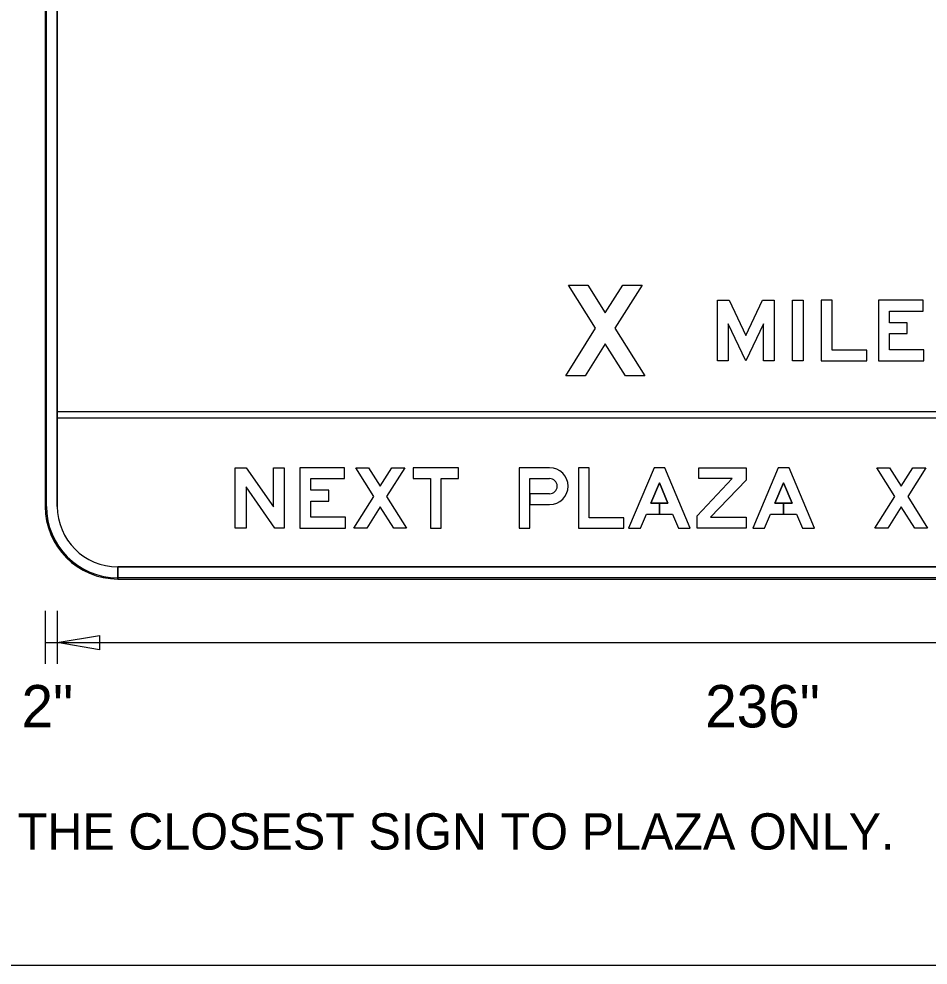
# Model space of a CAD drawing. Extents: x 17890484 to 17890754, y 17897495 to 17897992.
# Drawn here: x 17890528.32 to 17890540.84, y 17897572.57 to 17897585.59 of the extents above; entities that cross this region are included whole.
import ezdxf

# ---------------------------------------------------------------- set-up
doc = ezdxf.new("R2010")
doc.units = 0
for name, color, linetype in [('GSBWFill', 7, 'Continuous'), ('GSColorFill', 7, 'Continuous'), ('GSDims', 7, 'Continuous'), ('GSOutline', 7, 'Continuous'), ('SheetLinesMisc2_dp', 7, 'Continuous')]:
    doc.layers.add(name, color=color, linetype=linetype)

msp = doc.modelspace()

# ---------------------------------------------------------------- linework, layer by layer
at = {"layer": 'GSBWFill'}
for p, q in [((17890528.683, 17897590.883), (17890528.683, 17897578.883)), ((17890528.85, 17897578.883), (17890528.85, 17897590.883)), ((17890548.517, 17897580.186), (17890528.85, 17897580.186)), ((17890528.85, 17897580.186), (17890528.85, 17897580.103)), ((17890528.85, 17897580.103), (17890548.517, 17897580.103)), ((17890535.359, 17897579.265), (17890535.63, 17897579.265)), ((17890529.683, 17897577.883), (17890529.683, 17897578.049)), ((17890547.683, 17897578.049), (17890529.685, 17897578.049)), ((17890529.685, 17897578.049), (17890529.685, 17897577.883)), ((17890529.685, 17897577.883), (17890547.683, 17897577.883))]:
    msp.add_line(p, q, dxfattribs=at)
for points in [[(17890536.674, 17897580.678), (17890536.396, 17897581.121), (17890536.118, 17897580.678), (17890535.852, 17897580.678), (17890536.263, 17897581.333), (17890535.89, 17897581.928), (17890536.155, 17897581.928), (17890536.396, 17897581.544), (17890536.636, 17897581.928), (17890536.902, 17897581.928), (17890536.529, 17897581.333), (17890536.94, 17897580.678)], [(17890538.331, 17897581.235), (17890538.561, 17897581.719), (17890538.723, 17897581.719), (17890538.723, 17897580.886), (17890538.573, 17897580.886), (17890538.573, 17897581.394), (17890538.331, 17897580.886), (17890538.09, 17897581.394), (17890538.09, 17897580.886), (17890537.94, 17897580.886), (17890537.94, 17897581.719), (17890538.101, 17897581.719)], [(17890538.972, 17897580.886), (17890538.972, 17897581.719), (17890539.122, 17897581.719), (17890539.122, 17897580.886)], [(17890539.996, 17897580.886), (17890539.996, 17897581.032), (17890539.521, 17897581.032), (17890539.521, 17897581.719), (17890539.371, 17897581.719), (17890539.371, 17897580.886)], [(17890540.784, 17897581.036), (17890540.309, 17897581.036), (17890540.309, 17897581.26), (17890540.555, 17897581.26), (17890540.555, 17897581.41), (17890540.309, 17897581.41), (17890540.309, 17897581.569), (17890540.772, 17897581.569), (17890540.772, 17897581.719), (17890540.159, 17897581.719), (17890540.159, 17897580.886), (17890540.784, 17897580.886)], [(17890531.976, 17897579.415), (17890531.976, 17897578.582), (17890531.846, 17897578.582), (17890531.451, 17897579.152), (17890531.451, 17897578.582), (17890531.301, 17897578.582), (17890531.301, 17897579.415), (17890531.451, 17897579.415), (17890531.826, 17897578.875), (17890531.826, 17897579.415)], [(17890532.817, 17897578.732), (17890532.342, 17897578.732), (17890532.342, 17897578.956), (17890532.588, 17897578.956), (17890532.588, 17897579.106), (17890532.342, 17897579.106), (17890532.342, 17897579.265), (17890532.805, 17897579.265), (17890532.805, 17897579.415), (17890532.192, 17897579.415), (17890532.192, 17897578.582), (17890532.817, 17897578.582)], [(17890533.482, 17897578.582), (17890533.296, 17897578.877), (17890533.111, 17897578.582), (17890532.934, 17897578.582), (17890533.208, 17897579.018), (17890532.959, 17897579.415), (17890533.136, 17897579.415), (17890533.296, 17897579.159), (17890533.457, 17897579.415), (17890533.634, 17897579.415), (17890533.385, 17897579.018), (17890533.659, 17897578.582)], [(17890533.751, 17897579.265), (17890533.988, 17897579.265), (17890533.988, 17897578.582), (17890534.138, 17897578.582), (17890534.138, 17897579.265), (17890534.376, 17897579.265), (17890534.376, 17897579.415), (17890533.751, 17897579.415)], [(17890536.651, 17897578.582), (17890536.651, 17897578.727), (17890536.176, 17897578.727), (17890536.176, 17897579.415), (17890536.026, 17897579.415), (17890536.026, 17897578.582)], [(17890537.259, 17897578.927), (17890537.142, 17897578.927), (17890537.142, 17897578.777), (17890537.322, 17897578.777), (17890537.404, 17897578.582), (17890537.567, 17897578.582), (17890537.217, 17897579.415), (17890537.067, 17897579.415), (17890536.717, 17897578.582), (17890536.88, 17897578.582), (17890536.962, 17897578.777), (17890537.142, 17897578.777), (17890537.142, 17897578.927), (17890537.025, 17897578.927), (17890537.142, 17897579.206)], [(17890538.334, 17897578.732), (17890538.334, 17897578.582), (17890537.659, 17897578.582), (17890537.659, 17897578.752), (17890538.143, 17897579.265), (17890537.684, 17897579.265), (17890537.684, 17897579.415), (17890538.334, 17897579.415), (17890538.334, 17897579.244), (17890537.846, 17897578.732)], [(17890538.968, 17897578.927), (17890538.851, 17897578.927), (17890538.851, 17897578.777), (17890539.031, 17897578.777), (17890539.113, 17897578.582), (17890539.276, 17897578.582), (17890538.926, 17897579.415), (17890538.776, 17897579.415), (17890538.426, 17897578.582), (17890538.588, 17897578.582), (17890538.67, 17897578.777), (17890538.851, 17897578.777), (17890538.851, 17897578.927), (17890538.733, 17897578.927), (17890538.851, 17897579.206)], [(17890540.657, 17897578.582), (17890540.471, 17897578.877), (17890540.286, 17897578.582), (17890540.109, 17897578.582), (17890540.383, 17897579.018), (17890540.134, 17897579.415), (17890540.311, 17897579.415), (17890540.471, 17897579.159), (17890540.632, 17897579.415), (17890540.809, 17897579.415), (17890540.56, 17897579.018), (17890540.834, 17897578.582)]]:
    msp.add_lwpolyline(points, close=True, dxfattribs=at)
for points in [[(17890535.63, 17897579.415), (17890535.209, 17897579.415), (17890535.209, 17897578.582), (17890535.359, 17897578.582), (17890535.359, 17897579.265)], [(17890535.63, 17897579.057), (17890535.359, 17897579.057), (17890535.359, 17897578.907), (17890535.63, 17897578.907)]]:
    msp.add_lwpolyline(points, dxfattribs=at)
for radius in [1, 0.833]:
    msp.add_arc((17890529.683, 17897578.883), radius, 180, 270, dxfattribs=at)
for major_axis in [(0, 0.254), (0, 0.104)]:
    msp.add_ellipse((17890535.63, 17897579.161), major_axis=major_axis, ratio=0.999994, start_param=3.141593, end_param=6.283185, dxfattribs=at)
at = {"layer": 'GSColorFill'}
for p, q in [((17890528.683, 17897590.883), (17890528.683, 17897578.883)), ((17890528.683, 17897590.883), (17890528.683, 17897578.883)), ((17890528.683, 17897590.883), (17890528.683, 17897578.883)), ((17890528.7, 17897578.883), (17890528.7, 17897590.883)), ((17890528.85, 17897578.883), (17890528.85, 17897590.883)), ((17890548.517, 17897580.186), (17890528.85, 17897580.186)), ((17890528.85, 17897580.186), (17890528.85, 17897580.103)), ((17890528.85, 17897580.103), (17890548.517, 17897580.103)), ((17890535.359, 17897579.265), (17890535.63, 17897579.265)), ((17890529.683, 17897577.883), (17890529.683, 17897578.049)), ((17890547.683, 17897578.049), (17890529.685, 17897578.049)), ((17890529.685, 17897578.049), (17890529.685, 17897577.883)), ((17890529.683, 17897577.883), (17890529.683, 17897577.899)), ((17890547.683, 17897577.899), (17890529.683, 17897577.899)), ((17890529.683, 17897577.899), (17890529.683, 17897577.883)), ((17890529.683, 17897577.883), (17890547.683, 17897577.883)), ((17890529.683, 17897577.883), (17890547.683, 17897577.883)), ((17890529.685, 17897577.883), (17890547.683, 17897577.883))]:
    msp.add_line(p, q, dxfattribs=at)
for points in [[(17890536.674, 17897580.678), (17890536.396, 17897581.121), (17890536.118, 17897580.678), (17890535.852, 17897580.678), (17890536.263, 17897581.333), (17890535.89, 17897581.928), (17890536.155, 17897581.928), (17890536.396, 17897581.544), (17890536.636, 17897581.928), (17890536.902, 17897581.928), (17890536.529, 17897581.333), (17890536.94, 17897580.678)], [(17890538.331, 17897581.235), (17890538.561, 17897581.719), (17890538.723, 17897581.719), (17890538.723, 17897580.886), (17890538.573, 17897580.886), (17890538.573, 17897581.394), (17890538.331, 17897580.886), (17890538.09, 17897581.394), (17890538.09, 17897580.886), (17890537.94, 17897580.886), (17890537.94, 17897581.719), (17890538.101, 17897581.719)], [(17890538.972, 17897580.886), (17890538.972, 17897581.719), (17890539.122, 17897581.719), (17890539.122, 17897580.886)], [(17890539.996, 17897580.886), (17890539.996, 17897581.032), (17890539.521, 17897581.032), (17890539.521, 17897581.719), (17890539.371, 17897581.719), (17890539.371, 17897580.886)], [(17890540.784, 17897581.036), (17890540.309, 17897581.036), (17890540.309, 17897581.26), (17890540.555, 17897581.26), (17890540.555, 17897581.41), (17890540.309, 17897581.41), (17890540.309, 17897581.569), (17890540.772, 17897581.569), (17890540.772, 17897581.719), (17890540.159, 17897581.719), (17890540.159, 17897580.886), (17890540.784, 17897580.886)], [(17890531.976, 17897579.415), (17890531.976, 17897578.582), (17890531.846, 17897578.582), (17890531.451, 17897579.152), (17890531.451, 17897578.582), (17890531.301, 17897578.582), (17890531.301, 17897579.415), (17890531.451, 17897579.415), (17890531.826, 17897578.875), (17890531.826, 17897579.415)], [(17890532.817, 17897578.732), (17890532.342, 17897578.732), (17890532.342, 17897578.956), (17890532.588, 17897578.956), (17890532.588, 17897579.106), (17890532.342, 17897579.106), (17890532.342, 17897579.265), (17890532.805, 17897579.265), (17890532.805, 17897579.415), (17890532.192, 17897579.415), (17890532.192, 17897578.582), (17890532.817, 17897578.582)], [(17890533.482, 17897578.582), (17890533.296, 17897578.877), (17890533.111, 17897578.582), (17890532.934, 17897578.582), (17890533.208, 17897579.018), (17890532.959, 17897579.415), (17890533.136, 17897579.415), (17890533.296, 17897579.159), (17890533.457, 17897579.415), (17890533.634, 17897579.415), (17890533.385, 17897579.018), (17890533.659, 17897578.582)], [(17890533.751, 17897579.265), (17890533.988, 17897579.265), (17890533.988, 17897578.582), (17890534.138, 17897578.582), (17890534.138, 17897579.265), (17890534.376, 17897579.265), (17890534.376, 17897579.415), (17890533.751, 17897579.415)], [(17890536.651, 17897578.582), (17890536.651, 17897578.727), (17890536.176, 17897578.727), (17890536.176, 17897579.415), (17890536.026, 17897579.415), (17890536.026, 17897578.582)], [(17890537.259, 17897578.927), (17890537.142, 17897578.927), (17890537.142, 17897578.777), (17890537.322, 17897578.777), (17890537.404, 17897578.582), (17890537.567, 17897578.582), (17890537.217, 17897579.415), (17890537.067, 17897579.415), (17890536.717, 17897578.582), (17890536.88, 17897578.582), (17890536.962, 17897578.777), (17890537.142, 17897578.777), (17890537.142, 17897578.927), (17890537.025, 17897578.927), (17890537.142, 17897579.206)], [(17890538.334, 17897578.732), (17890538.334, 17897578.582), (17890537.659, 17897578.582), (17890537.659, 17897578.752), (17890538.143, 17897579.265), (17890537.684, 17897579.265), (17890537.684, 17897579.415), (17890538.334, 17897579.415), (17890538.334, 17897579.244), (17890537.846, 17897578.732)], [(17890538.968, 17897578.927), (17890538.851, 17897578.927), (17890538.851, 17897578.777), (17890539.031, 17897578.777), (17890539.113, 17897578.582), (17890539.276, 17897578.582), (17890538.926, 17897579.415), (17890538.776, 17897579.415), (17890538.426, 17897578.582), (17890538.588, 17897578.582), (17890538.67, 17897578.777), (17890538.851, 17897578.777), (17890538.851, 17897578.927), (17890538.733, 17897578.927), (17890538.851, 17897579.206)], [(17890540.657, 17897578.582), (17890540.471, 17897578.877), (17890540.286, 17897578.582), (17890540.109, 17897578.582), (17890540.383, 17897579.018), (17890540.134, 17897579.415), (17890540.311, 17897579.415), (17890540.471, 17897579.159), (17890540.632, 17897579.415), (17890540.809, 17897579.415), (17890540.56, 17897579.018), (17890540.834, 17897578.582)]]:
    msp.add_lwpolyline(points, close=True, dxfattribs=at)
for points in [[(17890535.63, 17897579.415), (17890535.209, 17897579.415), (17890535.209, 17897578.582), (17890535.359, 17897578.582), (17890535.359, 17897579.265)], [(17890535.63, 17897579.057), (17890535.359, 17897579.057), (17890535.359, 17897578.907), (17890535.63, 17897578.907)]]:
    msp.add_lwpolyline(points, dxfattribs=at)
for radius in [1, 1, 1, 0.983, 0.833]:
    msp.add_arc((17890529.683, 17897578.883), radius, 180, 270, dxfattribs=at)
for major_axis in [(0, 0.254), (0, 0.104)]:
    msp.add_ellipse((17890535.63, 17897579.161), major_axis=major_axis, ratio=0.999994, start_param=3.141593, end_param=6.283185, dxfattribs=at)
at = {"layer": 'GSDims'}
for p, q in [((17890528.683, 17897577.445), (17890528.683, 17897576.716)), ((17890528.85, 17897577.445), (17890528.85, 17897576.716)), ((17890528.85, 17897577.445), (17890528.85, 17897576.716)), ((17890528.683, 17897577.008), (17890528.85, 17897577.008)), ((17890528.85, 17897577.008), (17890548.517, 17897577.008))]:
    msp.add_line(p, q, dxfattribs=at)
msp.add_lwpolyline([(17890528.85, 17897577.008), (17890529.433, 17897577.105), (17890529.433, 17897576.91)], close=True, dxfattribs=at)
at = {"layer": 'GSOutline'}
for p, q in [((17890528.683, 17897590.883), (17890528.683, 17897578.883)), ((17890528.85, 17897590.883), (17890528.85, 17897578.883)), ((17890548.517, 17897580.186), (17890528.85, 17897580.186)), ((17890528.85, 17897580.186), (17890528.85, 17897580.103)), ((17890528.85, 17897580.103), (17890548.517, 17897580.103)), ((17890535.359, 17897579.265), (17890535.63, 17897579.265)), ((17890535.359, 17897578.907), (17890535.63, 17897578.907)), ((17890529.683, 17897578.049), (17890547.683, 17897578.049)), ((17890529.683, 17897577.883), (17890547.683, 17897577.883))]:
    msp.add_line(p, q, dxfattribs=at)
for points in [[(17890536.674, 17897580.678), (17890536.396, 17897581.121), (17890536.118, 17897580.678), (17890535.852, 17897580.678), (17890536.263, 17897581.333), (17890535.89, 17897581.928), (17890536.155, 17897581.928), (17890536.396, 17897581.544), (17890536.636, 17897581.928), (17890536.902, 17897581.928), (17890536.529, 17897581.333), (17890536.94, 17897580.678)], [(17890538.331, 17897581.235), (17890538.561, 17897581.719), (17890538.723, 17897581.719), (17890538.723, 17897580.886), (17890538.573, 17897580.886), (17890538.573, 17897581.394), (17890538.331, 17897580.886), (17890538.09, 17897581.394), (17890538.09, 17897580.886), (17890537.94, 17897580.886), (17890537.94, 17897581.719), (17890538.101, 17897581.719)], [(17890538.972, 17897580.886), (17890538.972, 17897581.719), (17890539.122, 17897581.719), (17890539.122, 17897580.886)], [(17890539.996, 17897580.886), (17890539.996, 17897581.032), (17890539.521, 17897581.032), (17890539.521, 17897581.719), (17890539.371, 17897581.719), (17890539.371, 17897580.886)], [(17890540.784, 17897581.036), (17890540.309, 17897581.036), (17890540.309, 17897581.26), (17890540.555, 17897581.26), (17890540.555, 17897581.41), (17890540.309, 17897581.41), (17890540.309, 17897581.569), (17890540.772, 17897581.569), (17890540.772, 17897581.719), (17890540.159, 17897581.719), (17890540.159, 17897580.886), (17890540.784, 17897580.886)], [(17890531.976, 17897579.415), (17890531.976, 17897578.582), (17890531.846, 17897578.582), (17890531.451, 17897579.152), (17890531.451, 17897578.582), (17890531.301, 17897578.582), (17890531.301, 17897579.415), (17890531.451, 17897579.415), (17890531.826, 17897578.875), (17890531.826, 17897579.415)], [(17890532.817, 17897578.732), (17890532.342, 17897578.732), (17890532.342, 17897578.956), (17890532.588, 17897578.956), (17890532.588, 17897579.106), (17890532.342, 17897579.106), (17890532.342, 17897579.265), (17890532.805, 17897579.265), (17890532.805, 17897579.415), (17890532.192, 17897579.415), (17890532.192, 17897578.582), (17890532.817, 17897578.582)], [(17890533.482, 17897578.582), (17890533.296, 17897578.877), (17890533.111, 17897578.582), (17890532.934, 17897578.582), (17890533.208, 17897579.018), (17890532.959, 17897579.415), (17890533.136, 17897579.415), (17890533.296, 17897579.159), (17890533.457, 17897579.415), (17890533.634, 17897579.415), (17890533.385, 17897579.018), (17890533.659, 17897578.582)], [(17890533.751, 17897579.265), (17890533.988, 17897579.265), (17890533.988, 17897578.582), (17890534.138, 17897578.582), (17890534.138, 17897579.265), (17890534.376, 17897579.265), (17890534.376, 17897579.415), (17890533.751, 17897579.415)], [(17890536.651, 17897578.582), (17890536.651, 17897578.727), (17890536.176, 17897578.727), (17890536.176, 17897579.415), (17890536.026, 17897579.415), (17890536.026, 17897578.582)], [(17890536.962, 17897578.777), (17890537.322, 17897578.777), (17890537.404, 17897578.582), (17890537.567, 17897578.582), (17890537.217, 17897579.415), (17890537.067, 17897579.415), (17890536.717, 17897578.582), (17890536.88, 17897578.582)], [(17890538.334, 17897578.732), (17890538.334, 17897578.582), (17890537.659, 17897578.582), (17890537.659, 17897578.752), (17890538.143, 17897579.265), (17890537.684, 17897579.265), (17890537.684, 17897579.415), (17890538.334, 17897579.415), (17890538.334, 17897579.244), (17890537.846, 17897578.732)], [(17890538.67, 17897578.777), (17890539.031, 17897578.777), (17890539.113, 17897578.582), (17890539.276, 17897578.582), (17890538.926, 17897579.415), (17890538.776, 17897579.415), (17890538.426, 17897578.582), (17890538.588, 17897578.582)], [(17890540.657, 17897578.582), (17890540.471, 17897578.877), (17890540.286, 17897578.582), (17890540.109, 17897578.582), (17890540.383, 17897579.018), (17890540.134, 17897579.415), (17890540.311, 17897579.415), (17890540.471, 17897579.159), (17890540.632, 17897579.415), (17890540.809, 17897579.415), (17890540.56, 17897579.018), (17890540.834, 17897578.582)], [(17890537.259, 17897578.927), (17890537.142, 17897579.206), (17890537.025, 17897578.927)], [(17890538.968, 17897578.927), (17890538.851, 17897579.206), (17890538.733, 17897578.927)]]:
    msp.add_lwpolyline(points, close=True, dxfattribs=at)
for points in [[(17890535.63, 17897579.415), (17890535.209, 17897579.415), (17890535.209, 17897578.582), (17890535.359, 17897578.582), (17890535.359, 17897578.907)], [(17890535.63, 17897579.057), (17890535.359, 17897579.057), (17890535.359, 17897579.265)]]:
    msp.add_lwpolyline(points, dxfattribs=at)
for radius in [1, 0.833]:
    msp.add_arc((17890529.683, 17897578.883), radius, 180, 270, dxfattribs=at)
for major_axis in [(0, 0.254), (0, 0.104)]:
    msp.add_ellipse((17890535.63, 17897579.161), major_axis=major_axis, ratio=0.999994, start_param=3.141593, end_param=6.283185, dxfattribs=at)
at = {"layer": 'SheetLinesMisc2_dp'}
msp.add_line((17890512.958, 17897572.57), (17890564.13, 17897572.57), dxfattribs=at)

# ---------------------------------------------------------------- texts
at = {"layer": 'GSDims'}
for s, height, p in [('2"', 0.5833, (17890528.358, 17897575.841)), ('236"', 0.5833, (17890537.772, 17897575.841)), ('NEXT PLAZA MESSAGE TO BE INSTALLED ON THE CLOSEST SIGN TO PLAZA ONLY.', 0.5, (17890513.331, 17897574.159))]:
    msp.add_text(s, height=height, dxfattribs=at).set_placement(p)

doc.saveas('drawing.dxf')
